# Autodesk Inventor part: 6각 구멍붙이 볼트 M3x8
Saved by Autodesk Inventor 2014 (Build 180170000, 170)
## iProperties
Created: 2026-06
Part Number: 6각 구멍붙이 볼트 M3x8
Material: 일반
Document SubType Name: Modeling
Designer: dg
Density: 1 g/cm^3
Appearance: 기본값
Author: dg
Author: jhkim
Description: 6각머리 태핑 나사
Creation Date: 2026-05-29
Sending System: Autodesk Inventor 2027
Preprocessor: ST-DEVELOPER v20.1
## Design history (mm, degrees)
node "6각 구멍붙이 볼트 M3x81"
body "Solid1"
node "기준1"
